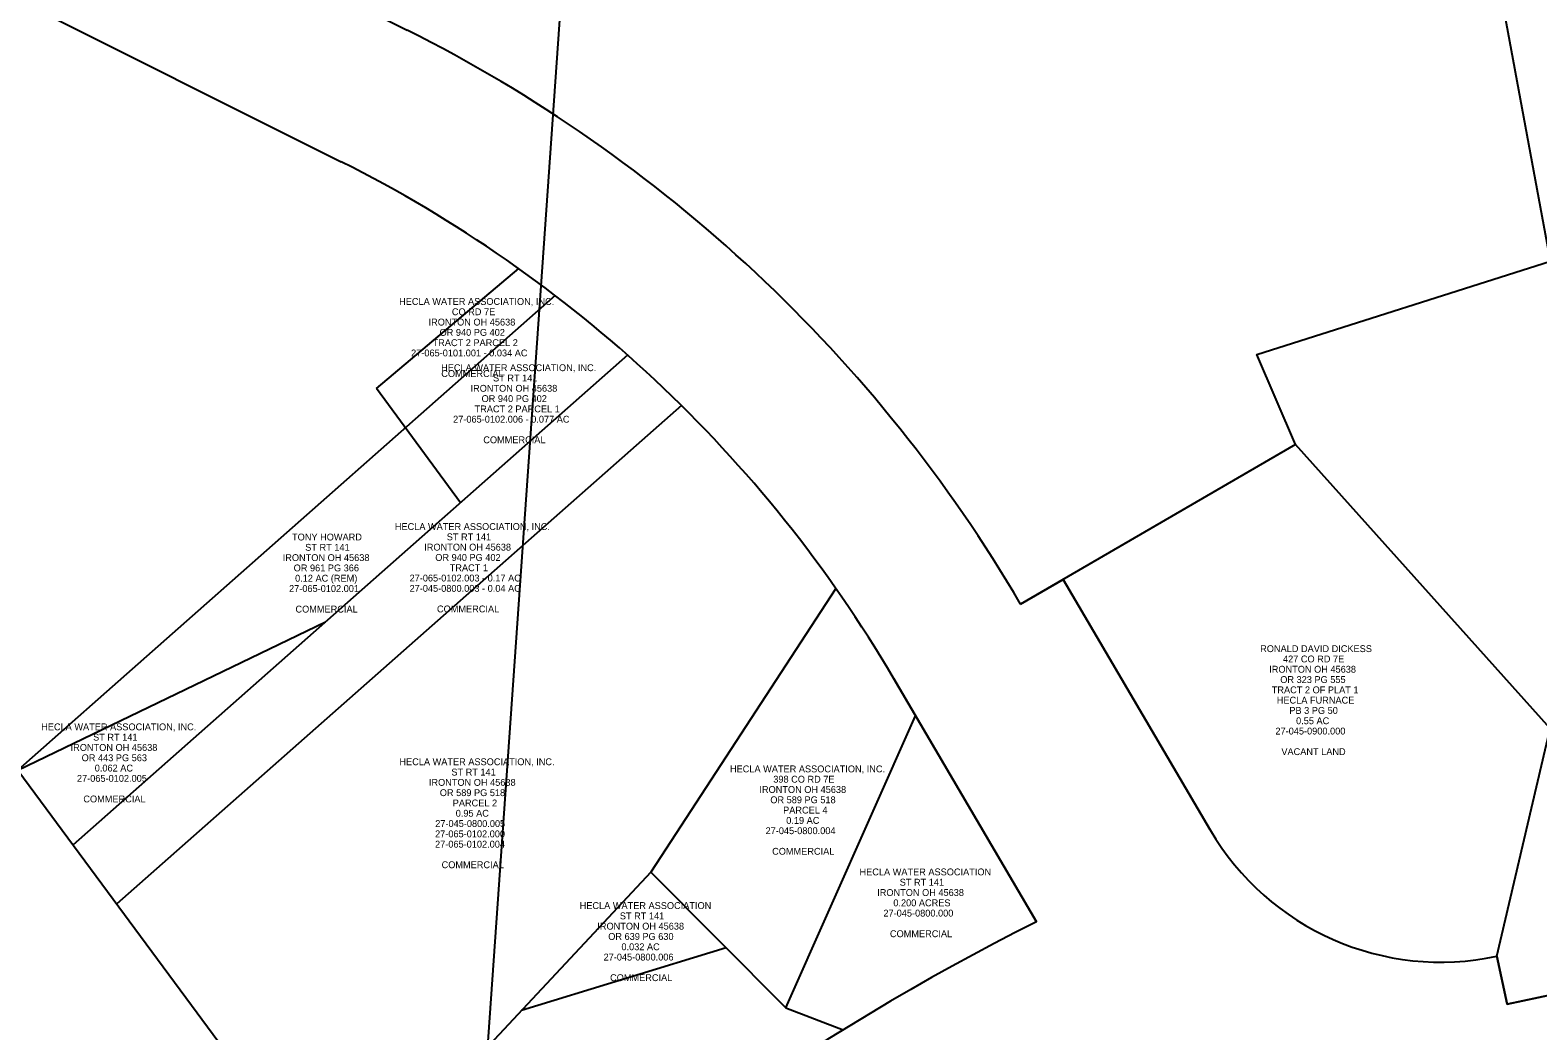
# Model space of a CAD drawing. Extents: x 1926695 to 1928303, y 198652 to 200926.
# Drawn here: x 1927197 to 1927812, y 199742 to 200150 of the extents above; entities that cross this region are included whole.
import ezdxf

# ---------------------------------------------------------------- set-up
doc = ezdxf.new("R2010")
doc.units = 0
for name, color, linetype in [('DV_X_Property_Line', 7, 'Continuous'), ('DV_X_Section_VMS_Line', 7, 'Continuous'), ('DV_X_Text', 7, 'Continuous'), ('RW_X_Fee_RW', 7, 'Continuous')]:
    doc.layers.add(name, color=color, linetype=linetype)

msp = doc.modelspace()

# ---------------------------------------------------------------- linework, layer by layer
at = {"layer": 'DV_X_Property_Line'}
for p, q in [((1927054.38, 200231.23), (1927323.97, 200096.26)), ((1927338.26, 200003.84), (1927396.33, 200052.68)), ((1927411.18, 200041.69), (1927192.02, 199848.17)), ((1927440.7, 200017.37), (1927214.57, 199817.69)), ((1927372.55, 199957.19), (1927338.26, 200003.84)), ((1927462.61, 199996.88), (1927232.4, 199793.6)), ((1927713.01, 199980.89), (1927600.94, 199915.88)), ((1927678.22, 199823.76), (1927618.24, 199925.92)), ((1927525.66, 199922.17), (1927450.16, 199806.6)), ((1927192.02, 199848.17), (1927317.58, 199908.65)), ((1927607.41, 199786.36), (1927549.12, 199885.64)), ((1927505.27, 199751.18), (1927558.14, 199870.28)), ((1927192.02, 199848.17), (1927363.59, 199616.33)), ((1927450.16, 199806.6), (1927323.3, 199670.77)), ((1927450.16, 199806.6), (1927505.27, 199751.18)), ((1927480.84, 199775.75), (1927397.43, 199750.14)), ((1927505.27, 199751.18), (1927528.62, 199742.32))]:
    msp.add_line(p, q, dxfattribs=at)
for points in [[(1927795.13, 199772.28), (1927816.89, 199865.18), (1927713.01, 199980.89), (1927697.26, 200017.66), (1927817.06, 200055.74), (1927729.84, 200526.35), (1927673.87, 200524.47), (1927316.35, 200167.17)], [(1927856.83, 199765), (1927799.31, 199752.72), (1927795.13, 199772.28)]]:
    msp.add_lwpolyline(points, dxfattribs=at)
for centre, radius, start, end in [((1927080.88, 199610.74), 602.97, 30.4018, 63.404), ((1927080.89, 199610.75), 542.96, 30.41641, 63.40416), ((1927772.34, 199879.02), 109.15, 210.41641, 282.05144), ((1928078.57, 198850.88), 1047.43, 116.73228, 150.49325)]:
    msp.add_arc(centre, radius, start, end, dxfattribs=at)
at = {"layer": 'DV_X_Section_VMS_Line'}
msp.add_line((1927376.1, 199627.83), (1927467.32, 200926.12), dxfattribs=at)
at = {"layer": 'RW_X_Fee_RW'}
for p, q in [((1926922.48, 200364.37), (1927350.83, 200149.91)), ((1927054.38, 200231.23), (1927323.97, 200096.26)), ((1927549.12, 199885.64), (1927607.41, 199786.36))]:
    msp.add_line(p, q, dxfattribs=at)
for points in [[(1927600.94, 199915.88), (1927618.24, 199925.92), (1927678.22, 199823.76)], [(1927795.13, 199772.28), (1927799.31, 199752.72), (1927856.83, 199765)]]:
    msp.add_lwpolyline(points, dxfattribs=at)
for centre, radius, start, end in [((1927080.88, 199610.74), 602.97, 30.4018, 63.404), ((1927080.89, 199610.75), 542.96, 30.41641, 63.40416), ((1927772.34, 199879.02), 109.15, 210.41641, 282.05144), ((1928078.57, 198850.88), 1047.43, 116.73228, 150.49325)]:
    msp.add_arc(centre, radius, start, end, dxfattribs=at)

# ---------------------------------------------------------------- texts
at = {"layer": 'DV_X_Text'}
for s, p in [('HECLA WATER ASSOCIATION, INC.', (1927347.54, 200037.87)), ('CO RD 7E', (1927369.05, 200033.67)), ('IRONTON OH 45638', (1927359.54, 200029.47)), ('TRACT 2 PARCEL 2', (1927361.19, 200021.07)), ('OR 940 PG 402', (1927364.03, 200025.27)), ('27-065-0101.001 - 0.034 AC', (1927352.42, 200016.87)), ('COMMERCIAL', (1927364.73, 200008.47)), ('HECLA WATER ASSOCIATION, INC.', (1927364.67, 200010.86)), ('IRONTON OH 45638', (1927376.66, 200002.46)), ('ST RT 141', (1927385.84, 200006.66)), ('OR 940 PG 402', (1927381.15, 199998.26)), ('27-065-0102.006 - 0.077 AC', (1927369.55, 199989.86)), ('TRACT 2 PARCEL 1', (1927378.31, 199994.06)), ('COMMERCIAL', (1927381.86, 199981.46)), ('TONY HOWARD', (1927303.88, 199941.82)), ('HECLA WATER ASSOCIATION, INC.', (1927345.79, 199946.09)), ('ST RT 141', (1927366.96, 199941.89)), ('ST RT 141', (1927309.26, 199937.62)), ('IRONTON OH 45638', (1927357.79, 199937.69)), ('IRONTON OH 45638', (1927300.08, 199933.42)), ('OR 961 PG 366', (1927304.54, 199929.22)), ('OR 940 PG 402', (1927362.28, 199933.49)), ('TRACT 1', (1927368.17, 199929.29)), ('0.12 AC (REM)', (1927305.12, 199925.02)), ('27-065-0102.003 - 0.17 AC', (1927351.79, 199925.09)), ('27-065-0102.001', (1927302.66, 199920.82)), ('27-045-0800.003 - 0.04 AC', (1927351.79, 199920.89)), ('COMMERCIAL', (1927305.28, 199912.42)), ('COMMERCIAL', (1927362.98, 199912.49)), ('RONALD DAVID DICKESS', (1927698.62, 199896.3)), ('427 CO RD 7E', (1927707.92, 199892.1)), ('IRONTON OH 45638', (1927702.31, 199887.9)), ('TRACT 2 OF PLAT 1', (1927703.35, 199879.5)), ('OR 323 PG 555', (1927706.81, 199883.7)), ('HECLA FURNACE', (1927705.4, 199875.3)), ('PB 3 PG 50', (1927710.51, 199871.1)), ('0.55 AC', (1927713.26, 199866.9)), ('HECLA WATER ASSOCIATION, INC.', (1927201.6, 199864.41)), ('ST RT 141', (1927222.77, 199860.21)), ('27-045-0900.000', (1927704.84, 199862.7)), ('IRONTON OH 45638', (1927213.6, 199856.01)), ('VACANT LAND', (1927707.26, 199854.3)), ('OR 443 PG 563', (1927218.1, 199851.81)), ('HECLA WATER ASSOCIATION, INC.', (1927347.67, 199850.18)), ('27-065-0102.005', (1927216.18, 199843.41)), ('0.062 AC', (1927223.43, 199847.61)), ('IRONTON OH 45638', (1927359.67, 199841.78)), ('ST RT 141', (1927368.84, 199845.98)), ('HECLA WATER ASSOCIATION, INC.', (1927482.44, 199847.27)), ('398 CO RD 7E', (1927500.1, 199843.07)), ('OR 589 PG 518', (1927364.13, 199837.58)), ('IRONTON OH 45638', (1927494.43, 199838.87)), ('COMMERCIAL', (1927218.79, 199835.01)), ('PARCEL 2', (1927369.4, 199833.38)), ('OR 589 PG 518', (1927498.89, 199834.67)), ('PARCEL 4', (1927504.11, 199830.47)), ('27-045-0800.005', (1927362.26, 199824.98)), ('0.95 AC', (1927370.61, 199829.18)), ('0.19 AC', (1927505.38, 199826.27)), ('27-065-0102.000', (1927362.2, 199820.78)), ('27-045-0800.004', (1927496.95, 199822.07)), ('27-065-0102.004', (1927362.19, 199816.58)), ('COMMERCIAL', (1927499.63, 199813.67)), ('COMMERCIAL', (1927364.86, 199808.18)), ('HECLA WATER ASSOCIATION', (1927535.26, 199805.26)), ('ST RT 141', (1927551.64, 199801.06)), ('IRONTON OH 45638', (1927542.47, 199796.86)), ('0.200 ACRES', (1927549.05, 199792.66)), ('HECLA WATER ASSOCIATION', (1927421.15, 199791.54)), ('ST RT 141', (1927437.53, 199787.34)), ('27-045-0800.000', (1927545, 199788.46)), ('IRONTON OH 45638', (1927428.35, 199783.14)), ('OR 639 PG 630', (1927432.8, 199778.94)), ('0.032 AC', (1927438.18, 199774.74)), ('COMMERCIAL', (1927547.66, 199780.06)), ('27-045-0800.006', (1927430.9, 199770.54)), ('COMMERCIAL', (1927433.55, 199762.14))]:
    msp.add_text(s, height=2.8, dxfattribs=at).set_placement(p)

doc.saveas('drawing.dxf')
